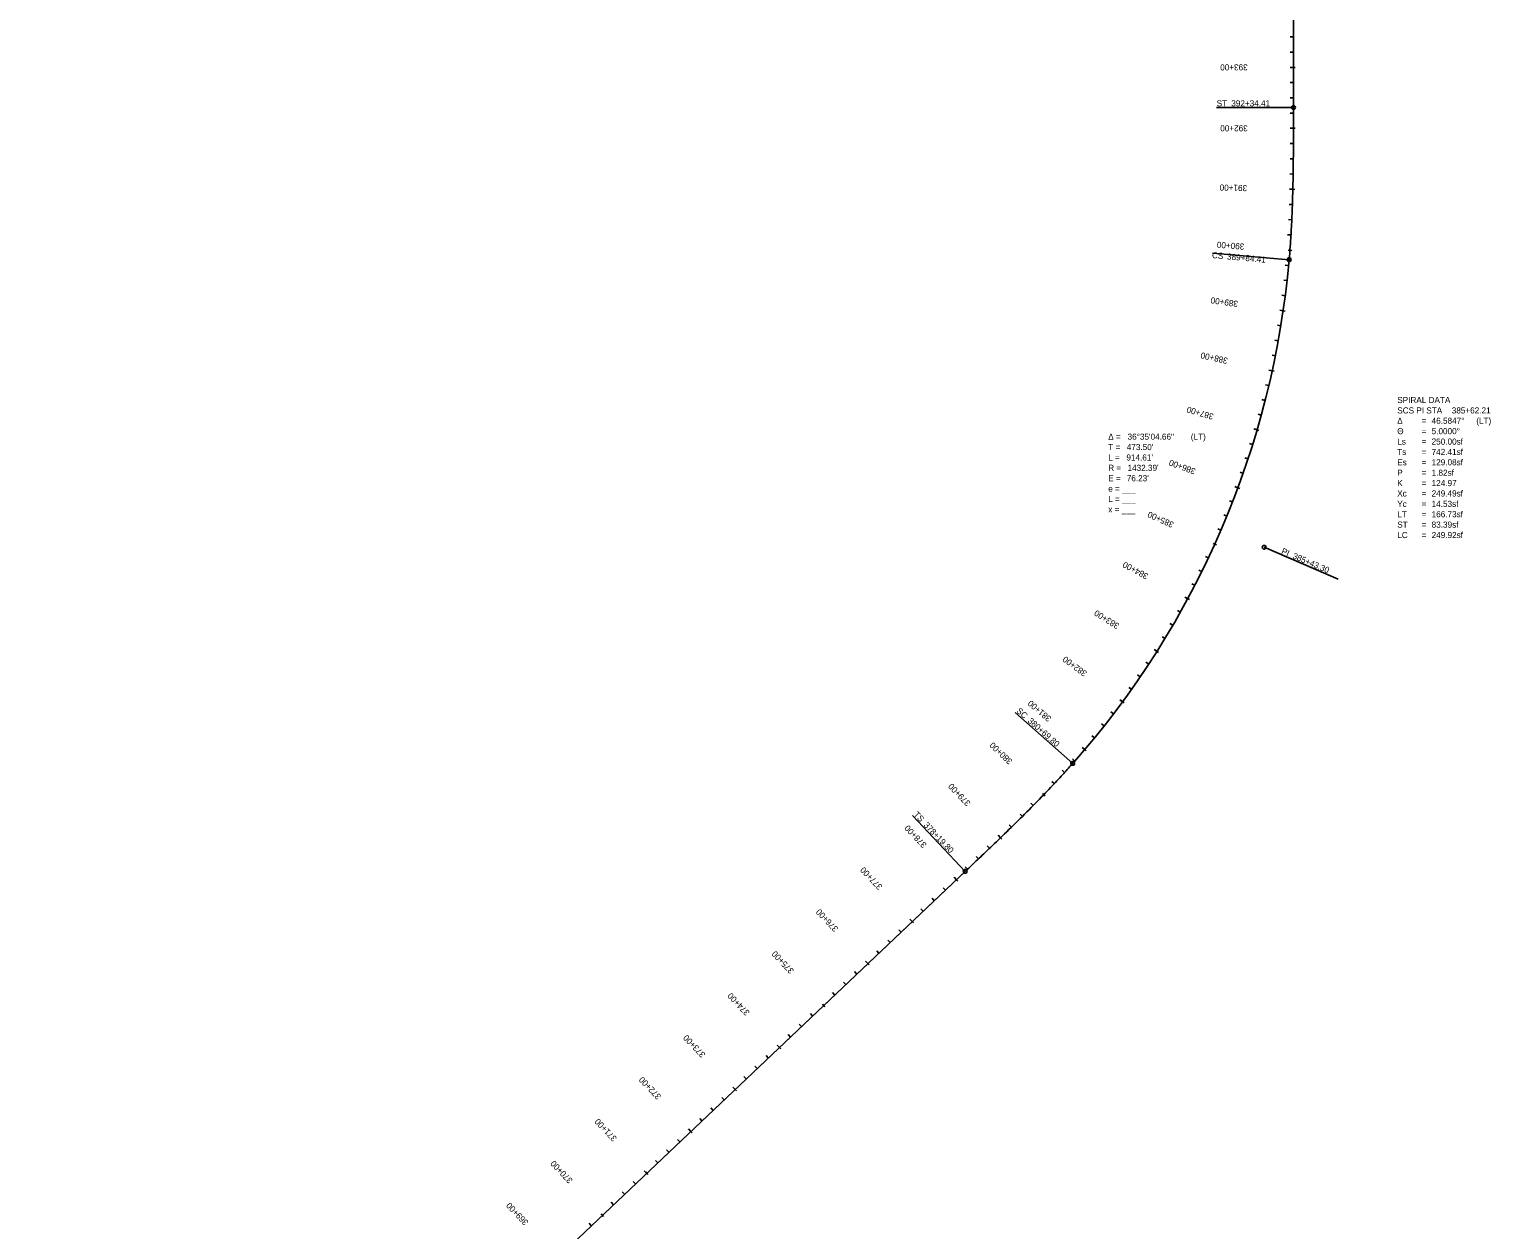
# Model space of a CAD drawing. Extents: x 23417911 to 23421158, y 6737892 to 6791804.
# Drawn here: x 23418761 to 23421158, y 6762891 to 6764860 of the extents above; entities that cross this region are included whole.
import ezdxf

# ---------------------------------------------------------------- set-up
doc = ezdxf.new("R2010")
doc.units = 0
for name, color, linetype in [('Alignment', 7, 'Continuous'), ('TextAlignment', 7, 'Continuous'), ('TextAlignmentLrg', 7, 'Continuous'), ('TextAlignmentSml', 7, 'Continuous')]:
    doc.layers.add(name, color=color, linetype=linetype)

msp = doc.modelspace()

# ---------------------------------------------------------------- linework, layer by layer
at = {"layer": 'Alignment'}
for p, q in [((23420834.6, 6764732), (23420829.5, 6771769.1)), ((23420834.6, 6764732), (23420829.5, 6771769.1)), ((23418761.1, 6762024.4), (23420297.1, 6763479.8)), ((23418761.1, 6762024.4), (23420296.2, 6763479)), ((23418761.1, 6762024.4), (23420296.2, 6763479))]:
    msp.add_line(p, q, dxfattribs=at)
msp.add_arc((23419400.4, 6764606), 1432.4, 318.4569, 355.0416, dxfattribs=at)
msp.add_arc((23419400.4, 6764606), 1432.4, 318.4569, 355.0416, dxfattribs=at)
for points in [[(23420827.5, 6764482.2), (23420828.1, 6764489.1), (23420829.2, 6764503), (23420831, 6764530.7), (23420832.7, 6764565.4), (23420833.8, 6764607), (23420834.4, 6764648.7), (23420834.6, 6764683.4), (23420834.6, 6764711.2), (23420834.6, 6764725.1), (23420834.6, 6764732)], [(23420827.5, 6764482.2), (23420828.1, 6764489.1), (23420829.2, 6764503), (23420831, 6764530.7), (23420832.7, 6764565.4), (23420833.8, 6764607), (23420834.4, 6764648.7), (23420834.6, 6764683.4), (23420834.6, 6764711.2), (23420834.6, 6764725.1), (23420834.6, 6764732)], [(23420296.2, 6763479), (23420301.2, 6763483.7), (23420311.3, 6763493.3), (23420331.5, 6763512.4), (23420356.5, 6763536.4), (23420386.4, 6763565.5), (23420415.8, 6763595.1), (23420439.8, 6763620.1), (23420458.6, 6763640.5), (23420467.9, 6763650.9), (23420472.5, 6763656.1)], [(23420296.2, 6763479), (23420301.2, 6763483.7), (23420311.3, 6763493.3), (23420331.5, 6763512.4), (23420356.5, 6763536.4), (23420386.4, 6763565.5), (23420415.8, 6763595.1), (23420439.8, 6763620.1), (23420458.6, 6763640.5), (23420467.9, 6763650.9), (23420472.5, 6763656.1)]]:
    msp.add_open_spline(points, degree=3, dxfattribs=at)
at = {"layer": 'TextAlignment'}
for p, q in [((23420834.6, 6764732), (23420708.6, 6764731.9)), ((23420708.6, 6764731.9), (23420708.6, 6764731.9)), ((23420827.5, 6764482.2), (23420701.9, 6764493.1)), ((23420701.9, 6764493.1), (23420701.9, 6764493.1)), ((23420827.5, 6764482.2), (23420701.9, 6764493.1)), ((23420701.9, 6764493.1), (23420701.9, 6764493.1)), ((23420786.5, 6764010.5), (23420907.8, 6763958.4)), ((23420907.8, 6763958.4), (23420907.8, 6763958.4)), ((23420472.5, 6763656.1), (23420378.2, 6763739.6)), ((23420378.2, 6763739.6), (23420378.2, 6763739.6)), ((23420472.5, 6763656.1), (23420378.2, 6763739.6)), ((23420378.2, 6763739.6), (23420378.2, 6763739.6)), ((23420296.2, 6763479), (23420209.5, 6763570.4)), ((23420209.5, 6763570.4), (23420209.5, 6763570.4))]:
    msp.add_line(p, q, dxfattribs=at)
for centre in [(23420834.6, 6764732), (23420827.5, 6764482.2), (23420827.5, 6764482.2), (23420786.5, 6764010.5), (23420472.5, 6763656.1), (23420472.5, 6763656.1), (23420296.2, 6763479)]:
    msp.add_circle(centre, 3.12, dxfattribs=at)
at = {"layer": 'TextAlignmentLrg'}
for p, q in [((23420834.5, 6764797.6), (23420829.1, 6764797.6)), ((23420834.6, 6764697.6), (23420829.1, 6764697.6)), ((23420833.5, 6764597.6), (23420828.1, 6764597.7)), ((23420825.7, 6764498), (23420831.8, 6764497.5)), ((23420817.7, 6764398.4), (23420812.3, 6764399.2)), ((23420799.8, 6764300), (23420794.4, 6764301.2)), ((23420775, 6764203.1), (23420769.8, 6764204.7)), ((23420743.6, 6764108.2), (23420738.4, 6764110.1)), ((23420702.8, 6764017), (23420708.4, 6764014.5)), ((23420661.2, 6763926.2), (23420656.4, 6763928.7)), ((23420610.7, 6763839.9), (23420606.1, 6763842.8)), ((23420554.3, 6763757.3), (23420549.9, 6763760.5)), ((23420492.3, 6763678.9), (23420488.2, 6763682.4)), ((23420422.9, 6763607), (23420427.3, 6763602.7)), ((23420354.2, 6763534.3), (23420350.5, 6763538.2)), ((23420281.8, 6763465.4), (23420278.1, 6763469.3)), ((23420209.2, 6763396.6), (23420205.5, 6763400.5)), ((23420136.6, 6763327.8), (23420132.9, 6763331.8)), ((23420061.9, 6763261.2), (23420066.2, 6763256.8)), ((23419991.5, 6763190.2), (23419987.7, 6763194.2)), ((23419918.9, 6763121.5), (23419915.1, 6763125.4)), ((23419846.3, 6763052.7), (23419842.5, 6763056.6)), ((23419773.7, 6762983.9), (23419769.9, 6762987.9)), ((23419699, 6762917.3), (23419703.2, 6762912.9))]:
    msp.add_line(p, q, dxfattribs=at)
at = {"layer": 'TextAlignmentSml'}
for p, q in [((23420834.5, 6764847.6), (23420829, 6764847.6)), ((23420834.5, 6764822.6), (23420829, 6764822.6)), ((23420831.5, 6764797.6), (23420837.6, 6764797.6)), ((23420834.5, 6764772.6), (23420829.1, 6764772.6)), ((23420834.5, 6764747.6), (23420829.1, 6764747.6)), ((23420834.6, 6764722.6), (23420829.1, 6764722.6)), ((23420831.5, 6764697.6), (23420837.6, 6764697.6)), ((23420834.5, 6764672.6), (23420829, 6764672.6)), ((23420834.3, 6764647.6), (23420828.9, 6764647.7)), ((23420834, 6764622.6), (23420828.6, 6764622.7)), ((23420830.5, 6764597.7), (23420836.6, 6764597.5)), ((23420832.8, 6764572.6), (23420827.3, 6764572.8)), ((23420831.8, 6764547.6), (23420826.3, 6764547.9)), ((23420830.4, 6764522.7), (23420825, 6764523)), ((23420825.7, 6764498), (23420831.8, 6764497.5)), ((23420826.6, 6764472.8), (23420821.2, 6764473.3)), ((23420824.1, 6764448), (23420818.7, 6764448.6)), ((23420821.1, 6764423.1), (23420815.7, 6764423.8)), ((23420814.7, 6764398.8), (23420820.7, 6764397.9)), ((23420813.9, 6764373.7), (23420808.5, 6764374.6)), ((23420809.6, 6764349), (23420804.2, 6764350)), ((23420804.9, 6764324.5), (23420799.5, 6764325.6)), ((23420796.8, 6764300.7), (23420802.8, 6764299.4)), ((23420794.2, 6764275.6), (23420788.9, 6764276.9)), ((23420788.2, 6764251.4), (23420782.9, 6764252.7)), ((23420781.8, 6764227.2), (23420776.6, 6764228.6)), ((23420772.1, 6764204), (23420778, 6764202.3)), ((23420767.8, 6764179.2), (23420762.6, 6764180.8)), ((23420760.1, 6764155.4), (23420754.9, 6764157.1)), ((23420752, 6764131.8), (23420746.9, 6764133.6)), ((23420740.7, 6764109.3), (23420746.4, 6764107.2)), ((23420734.7, 6764084.9), (23420729.6, 6764086.9)), ((23420725.4, 6764061.7), (23420720.3, 6764063.7)), ((23420715.7, 6764038.6), (23420710.7, 6764040.8)), ((23420702.8, 6764017), (23420708.4, 6764014.5)), ((23420695.1, 6763993.1), (23420690.1, 6763995.4)), ((23420684.2, 6763970.6), (23420679.3, 6763973)), ((23420672.9, 6763948.3), (23420668, 6763950.8)), ((23420658.5, 6763927.6), (23420663.9, 6763924.7)), ((23420649.2, 6763904.3), (23420644.4, 6763906.9)), ((23420636.7, 6763882.6), (23420632, 6763885.3)), ((23420608.1, 6763841.5), (23420613.3, 6763838.2)), ((23420623.9, 6763861.1), (23420619.2, 6763863.9)), ((23420597.2, 6763818.9), (23420592.6, 6763821.9)), ((23420583.2, 6763798.1), (23420578.7, 6763801.2)), ((23420569, 6763777.6), (23420564.5, 6763780.7)), ((23420551.9, 6763759.1), (23420556.8, 6763755.5)), ((23420524, 6763717.6), (23420519.7, 6763720.9)), ((23420539.3, 6763737.3), (23420535, 6763740.6)), ((23420508.3, 6763698.1), (23420504.1, 6763701.5)), ((23420490, 6763680.9), (23420494.6, 6763676.9)), ((23420476, 6763660), (23420471.9, 6763663.6)), ((23420442.3, 6763623), (23420438.3, 6763626.7)), ((23420459.3, 6763641.3), (23420455.3, 6763645)), ((23420422.9, 6763607), (23420427.3, 6763602.7)), ((23420407.6, 6763587), (23420403.8, 6763590.8)), ((23420372.2, 6763551.7), (23420368.4, 6763555.6)), ((23420390, 6763569.3), (23420386.1, 6763573.1)), ((23420352.1, 6763536.5), (23420356.4, 6763532.1)), ((23420336.2, 6763517), (23420332.4, 6763520.9)), ((23420300, 6763482.6), (23420296.2, 6763486.5)), ((23420318.1, 6763499.8), (23420314.3, 6763503.7)), ((23420279.7, 6763467.6), (23420283.9, 6763463.1)), ((23420245.5, 6763431), (23420241.8, 6763434.9)), ((23420263.7, 6763448.2), (23420259.9, 6763452.1)), ((23420227.4, 6763413.8), (23420223.6, 6763417.7)), ((23420207.1, 6763398.8), (23420211.3, 6763394.4)), ((23420172.9, 6763362.2), (23420169.2, 6763366.1)), ((23420191.1, 6763379.4), (23420187.3, 6763383.3)), ((23420154.8, 6763345), (23420151, 6763349)), ((23420118.5, 6763310.6), (23420114.7, 6763314.6)), ((23420134.5, 6763330), (23420138.7, 6763325.6)), ((23420100.3, 6763293.4), (23420096.6, 6763297.4)), ((23420082.2, 6763276.2), (23420078.4, 6763280.2)), ((23420045.9, 6763241.8), (23420042.2, 6763245.8)), ((23420061.9, 6763261.2), (23420066.2, 6763256.8)), ((23420027.8, 6763224.6), (23420024, 6763228.6)), ((23420009.6, 6763207.4), (23420005.9, 6763211.4)), ((23419973.3, 6763173), (23419969.6, 6763177)), ((23419989.4, 6763192.5), (23419993.6, 6763188)), ((23419955.2, 6763155.8), (23419951.4, 6763159.8)), ((23419916.8, 6763123.7), (23419921, 6763119.2)), ((23419937, 6763138.6), (23419933.3, 6763142.6)), ((23419900.7, 6763104.3), (23419897, 6763108.2)), ((23419864.4, 6763069.9), (23419860.7, 6763073.8)), ((23419882.6, 6763087.1), (23419878.8, 6763091)), ((23419844.2, 6763054.9), (23419848.4, 6763050.4)), ((23419828.1, 6763035.5), (23419824.4, 6763039.4)), ((23419791.8, 6763001.1), (23419788.1, 6763005)), ((23419810, 6763018.3), (23419806.2, 6763022.2)), ((23419771.6, 6762986.1), (23419775.8, 6762981.7)), ((23419755.5, 6762966.7), (23419751.8, 6762970.7)), ((23419719.3, 6762932.3), (23419715.5, 6762936.3)), ((23419737.4, 6762949.5), (23419733.6, 6762953.5)), ((23419699, 6762917.3), (23419703.2, 6762912.9)), ((23419683, 6762897.9), (23419679.2, 6762901.9))]:
    msp.add_line(p, q, dxfattribs=at)

# ---------------------------------------------------------------- texts
at = {"layer": 'TextAlignment'}
for s, rotation, p in [('ST', 0.0416, (23420708.6, 6764733.6)), ('392+34.41', 0.0416, (23420732.6, 6764733.6)), ('CS', 355.0416, (23420700.6, 6764484.8)), ('389+84.41', 355.0416, (23420725.3, 6764482.6)), ('PI ', 336.7492, (23420813.8, 6764000.6)), ('385+43.30', 336.7492, (23420832.2, 6763992.7)), ('SC', 318.4569, (23420379.3, 6763740.9)), ('SC', 318.4569, (23420379.3, 6763740.9)), ('380+69.80', 318.4569, (23420397.9, 6763724.5)), ('380+69.80', 318.4569, (23420397.9, 6763724.5)), ('TS', 313.4569, (23420210.8, 6763571.6)), ('378+19.80', 313.4569, (23420227.3, 6763554.1))]:
    msp.add_text(s, height=10.02, rotation=rotation, dxfattribs=at).set_placement(p)
for s, height, p in [('SPIRAL DATA', 10.02, (23421004.8, 6764247.1)), ('SCS PI STA ', 10.02, (23421004.8, 6764230)), ('385+62.21', 10.02, (23421094.2, 6764230)), ('Δ', 10, (23421004.8, 6764213)), ('Θ ', 10.02, (23421004.8, 6764196)), ('= ', 10.02, (23421044.9, 6764213)), ('= ', 10.02, (23421044.9, 6764196)), ('46.5847°', 10.02, (23421061.2, 6764213)), ('5.0000°', 10.02, (23421061.2, 6764196)), (' (LT)', 10.02, (23421130.7, 6764213)), ('Δ = ', 10.02, (23420530.8, 6764186.9)), ('T = ', 10.02, (23420530.8, 6764169.9)), ("473.50'", 10.02, (23420561.2, 6764169.9)), ('36°35\'04.66"', 10.02, (23420562.5, 6764186.9)), (' (LT)', 10.02, (23420662.5, 6764186.9)), ('Ls', 10.02, (23421004.8, 6764178.9)), ('= ', 10.02, (23421044.9, 6764178.9)), ('250.00sf', 10.02, (23421061.2, 6764178.9)), ('L = ', 10.02, (23420530.8, 6764152.8)), ("914.61'", 10.02, (23420560.6, 6764152.8)), ('Ts', 10.02, (23421004.8, 6764161.9)), ('Es', 10.02, (23421004.8, 6764144.9)), ('= ', 10.02, (23421044.9, 6764161.9)), ('742.41sf', 10.02, (23421061.2, 6764161.9)), ('129.08sf', 10.02, (23421061.2, 6764144.9)), ('R = ', 10.02, (23420530.8, 6764135.8)), ('E = ', 10.02, (23420530.8, 6764118.8)), ("76.23'", 10.02, (23420561.2, 6764118.8)), ("1432.39'", 10.02, (23420562.4, 6764135.8)), ('P', 10, (23421004.8, 6764127.8)), ('= ', 10.02, (23421044.9, 6764144.9)), ('= ', 10.02, (23421044.9, 6764127.8)), ('1.82sf', 10.02, (23421061.2, 6764127.8)), ('e = ___ ', 10.02, (23420530.8, 6764101.7)), ('K', 10, (23421004.8, 6764110.8)), ('= ', 10.02, (23421044.9, 6764110.8)), ('249.49sf', 10.02, (23421061.2, 6764093.8)), ('124.97', 10.02, (23421061.2, 6764110.8)), ('L = ___', 10.02, (23420530.8, 6764084.7)), ('Xc', 10.02, (23421004.8, 6764093.8)), ('Yc', 10.02, (23421004.8, 6764076.7)), ('= ', 10.02, (23421044.9, 6764093.8)), ('= ', 10.02, (23421044.9, 6764076.7)), ('14.53sf', 10.02, (23421061.2, 6764076.7)), ('x = ___', 10.02, (23420530.8, 6764067.7)), ('LT', 10.02, (23421004.8, 6764059.7)), ('= ', 10.02, (23421044.9, 6764059.7)), ('166.73sf', 10.02, (23421061.2, 6764059.7)), ('ST ', 10.02, (23421004.8, 6764042.7)), ('LC', 10.02, (23421004.8, 6764025.6)), ('= ', 10.02, (23421044.9, 6764042.7)), ('= ', 10.02, (23421044.9, 6764025.6)), ('83.39sf', 10.02, (23421061.2, 6764042.7)), ('249.92sf', 10.02, (23421061.2, 6764025.6))]:
    msp.add_text(s, height=height, dxfattribs=at).set_placement(p)
at = {"layer": 'TextAlignmentLrg'}
for s, rotation, p in [('390+00', 175.6457, (23420754.3, 6764508.4)), ('385+00', 155.6651, (23420639.3, 6764051.2)), ('380+00', 136.0548, (23420374.6, 6763660.5)), ('375+00', 133.4569, (23420016.1, 6763316.9)), ('370+00', 133.4569, (23419653.2, 6762973))]:
    msp.add_text(s, height=10.02, rotation=rotation, dxfattribs=at).set_placement(p)
at = {"layer": 'TextAlignmentSml'}
for s, rotation, p in [('393+00', 180.0416, (23420759.5, 6764802.6)), ('392+00', 179.9468, (23420759.6, 6764702.7)), ('391+00', 178.5963, (23420758.7, 6764604.5)), ('390+00', 175.6457, (23420754.3, 6764508.4)), ('389+00', 171.6651, (23420744.2, 6764414.2)), ('388+00', 167.6651, (23420727.6, 6764320.9)), ('387+00', 163.6651, (23420704.5, 6764229)), ('386+00', 159.6651, (23420675, 6764139)), ('385+00', 155.6651, (23420639.3, 6764051.2)), ('384+00', 151.6651, (23420597.6, 6763966.2)), ('383+00', 147.6651, (23420550, 6763884.2)), ('382+00', 143.6651, (23420496.9, 6763805.8)), ('381+00', 139.665, (23420438.4, 6763731.2)), ('380+00', 136.0548, (23420374.6, 6763660.5)), ('379+00', 133.9715, (23420305.8, 6763591.8)), ('378+00', 133.4569, (23420233.9, 6763523.2)), ('377+00', 133.4569, (23420161.3, 6763454.5)), ('376+00', 133.4569, (23420088.7, 6763385.7)), ('375+00', 133.4569, (23420016.1, 6763316.9)), ('374+00', 133.4569, (23419943.5, 6763248.1)), ('373+00', 133.4569, (23419870.9, 6763179.3)), ('372+00', 133.4569, (23419798.3, 6763110.6)), ('371+00', 133.4569, (23419725.7, 6763041.8)), ('370+00', 133.4569, (23419653.2, 6762973)), ('369+00', 133.4569, (23419580.6, 6762904.2))]:
    msp.add_text(s, height=10.02, rotation=rotation, dxfattribs=at).set_placement(p)

doc.saveas('drawing.dxf')
